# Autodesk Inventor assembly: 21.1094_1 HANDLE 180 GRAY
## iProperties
Created: 2007-03
Part Number: 21.1094_1 HANDLE 180 GRAY
Document SubType Name: Assembly
Designer: Andy Moles
Mass: 95.0172 g
Surface Area: 251.455 cm^2
Volume: 61.8162 cm^3
Density: 1.53709 g/cm^3
Author: Andy Moles
